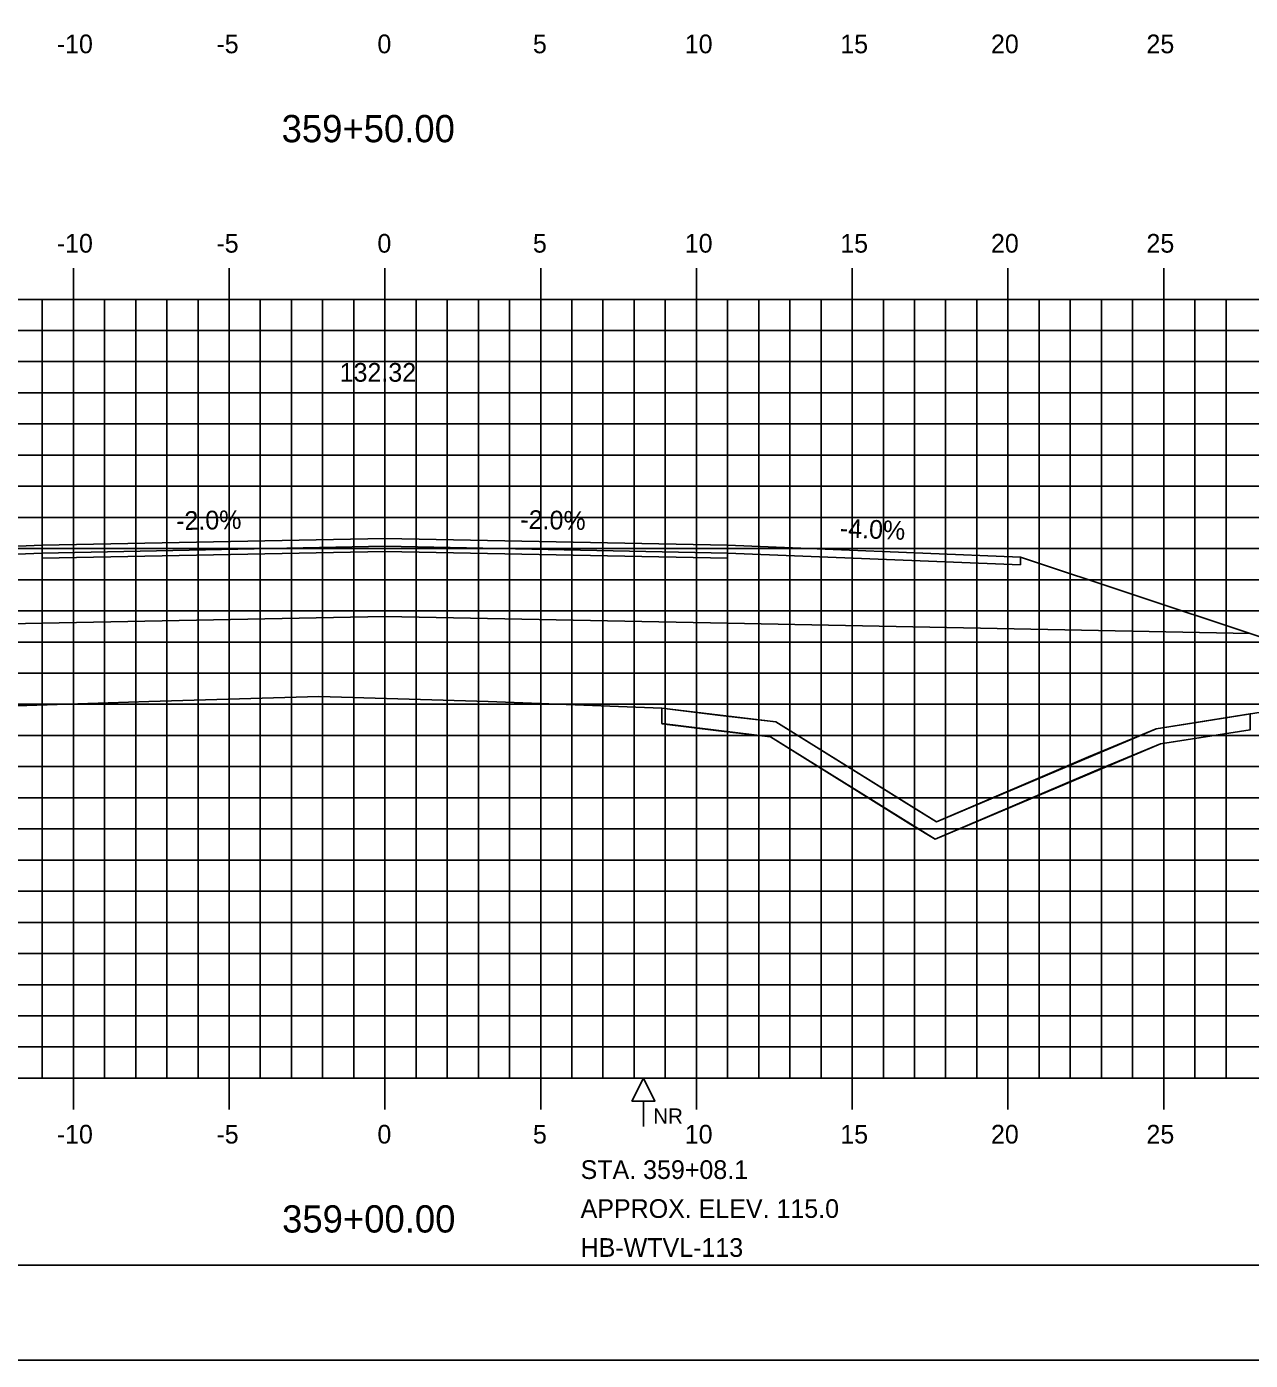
# Model space of a CAD drawing. Extents: x 1146303 to 1146473, y 608981 to 609091.
# Drawn here: x 1146374.41 to 1146413.69, y 608981.28 to 609024.09 of the extents above; entities that cross this region are included whole.
import ezdxf

# ---------------------------------------------------------------- set-up
doc = ezdxf.new("R2010")
doc.units = 0
for name, color, linetype in [('ANNOTATION', 7, 'Continuous'), ('BORDER', 7, 'Continuous'), ('D_Roadway_Centerline', 7, 'Continuous'), ('D_Roadway_Centerline_Text', 7, 'Continuous'), ('D_Roadway_Edge_Shoulder', 7, 'Continuous'), ('D_Roadway_Edge_TW', 7, 'Continuous'), ('D_Roadway_Pavement', 7, 'Continuous'), ('D_Roadway_SubGrade', 7, 'Continuous'), ('H_V ANNOTATION', 7, 'Continuous'), ('MAJOR', 7, 'Continuous'), ('MINOR', 7, 'Continuous'), ('PLOT BOUNDARY', 7, 'Continuous'), ('ROCKS', 7, 'Continuous'), ('S_Roadway_Centerline', 7, 'Continuous'), ('SHADING', 7, 'Continuous')]:
    doc.layers.add(name, color=color, linetype=linetype)

msp = doc.modelspace()

# ---------------------------------------------------------------- linework, layer by layer
msp.add_lwpolyline([(1146341.288, 608998.284), (1146357.382, 609003.649), (1146360.382, 609004.649), (1146367.914, 609007.159), (1146367.915, 609007.159), (1146374.915, 609007.439), (1146385.915, 609007.659), (1146396.915, 609007.439), (1146406.316, 609007.063), (1146413.695, 609004.604), (1146416.695, 609003.604), (1146418.924, 609002.861)])
at = {"layer": 'BORDER'}
msp.add_lwpolyline([(1146310.915, 608984.335), (1146470.915, 608984.335), (1146470.915, 609089.335), (1146310.915, 609089.335)], close=True, dxfattribs=at)
at = {"layer": 'D_Roadway_Edge_Shoulder'}
for points in [[(1146374.915, 609007.439), (1146367.915, 609007.159), (1146367.915, 609006.909), (1146374.915, 609007.189)], [(1146396.915, 609007.439), (1146406.316, 609007.063), (1146406.316, 609006.813), (1146396.915, 609007.189)]]:
    msp.add_lwpolyline(points, close=True, dxfattribs=at)
at = {"layer": 'D_Roadway_Edge_TW'}
msp.add_lwpolyline([(1146374.915, 609007.189), (1146374.915, 609007.439), (1146385.915, 609007.659), (1146396.915, 609007.439), (1146396.915, 609007.189), (1146385.915, 609007.409)], close=True, dxfattribs=at)
at = {"layer": 'D_Roadway_Pavement'}
msp.add_lwpolyline([(1146374.915, 609007.023), (1146374.915, 609007.189), (1146385.915, 609007.409), (1146396.915, 609007.189), (1146396.915, 609007.023), (1146385.915, 609007.243)], close=True, dxfattribs=at)
at = {"layer": 'D_Roadway_SubGrade'}
for p, q in [((1146394.809, 609002.215), (1146394.809, 609001.715)), ((1146413.695, 609002.025), (1146413.695, 609001.52))]:
    msp.add_line(p, q, dxfattribs=at)
for points in [[(1146374.915, 609007.023), (1146374.915, 609007.189), (1146367.915, 609006.909), (1146367.915, 609007.159), (1146367.914, 609007.159), (1146360.382, 609004.649), (1146374.915, 609004.939)], [(1146374.915, 609004.939), (1146374.915, 609007.023), (1146385.915, 609007.243), (1146396.915, 609007.023), (1146396.915, 609004.939), (1146385.915, 609005.159)], [(1146396.915, 609007.023), (1146396.915, 609007.189), (1146406.316, 609006.813), (1146406.316, 609007.063), (1146406.316, 609007.063), (1146413.695, 609004.604), (1146396.915, 609004.939)]]:
    msp.add_lwpolyline(points, close=True, dxfattribs=at)
msp.add_lwpolyline([(1146394.809, 609001.712), (1146396.623, 609001.482), (1146398.295, 609001.291), (1146402.801, 608998.475), (1146403.578, 608998.007), (1146408.695, 609000.193), (1146410.812, 609001.067), (1146412.113, 609001.267), (1146413.695, 609001.52)], dxfattribs=at)
at = {"layer": 'MAJOR'}
for p, q in [((1146375.915, 609016.337), (1146375.915, 609015.335)), ((1146380.915, 609016.337), (1146380.915, 609015.335)), ((1146385.915, 609016.337), (1146385.915, 609015.335)), ((1146390.915, 609016.337), (1146390.915, 609015.335)), ((1146395.915, 609016.337), (1146395.915, 609015.335)), ((1146400.915, 609016.337), (1146400.915, 609015.335)), ((1146405.915, 609016.337), (1146405.915, 609015.335)), ((1146410.915, 609016.337), (1146410.915, 609015.335)), ((1146315.915, 609015.335), (1146455.915, 609015.335)), ((1146315.915, 609015.335), (1146455.915, 609015.335)), ((1146375.915, 608990.335), (1146375.915, 609015.335)), ((1146380.915, 608990.335), (1146380.915, 609015.335)), ((1146385.915, 608990.335), (1146385.915, 609015.335)), ((1146390.915, 608990.335), (1146390.915, 609015.335)), ((1146395.915, 608990.335), (1146395.915, 609015.335)), ((1146400.915, 608990.335), (1146400.915, 609015.335)), ((1146405.915, 608990.335), (1146405.915, 609015.335)), ((1146410.915, 608990.335), (1146410.915, 609015.335)), ((1146315.915, 609010.335), (1146455.915, 609010.335)), ((1146315.915, 609005.335), (1146455.915, 609005.335)), ((1146315.915, 609000.335), (1146455.915, 609000.335)), ((1146315.915, 608995.335), (1146455.915, 608995.335)), ((1146315.915, 608990.335), (1146455.915, 608990.335)), ((1146315.915, 608990.335), (1146455.915, 608990.335)), ((1146375.915, 608989.333), (1146375.915, 608990.335)), ((1146380.915, 608989.333), (1146380.915, 608990.335)), ((1146385.915, 608989.333), (1146385.915, 608990.335)), ((1146390.915, 608989.333), (1146390.915, 608990.335)), ((1146395.915, 608989.333), (1146395.915, 608990.335)), ((1146400.915, 608989.333), (1146400.915, 608990.335)), ((1146405.915, 608989.333), (1146405.915, 608990.335)), ((1146410.915, 608989.333), (1146410.915, 608990.335))]:
    msp.add_line(p, q, dxfattribs=at)
at = {"layer": 'MINOR'}
for p, q in [((1146374.915, 608990.335), (1146374.915, 609015.335)), ((1146376.915, 608990.335), (1146376.915, 609015.335)), ((1146377.915, 608990.335), (1146377.915, 609015.335)), ((1146378.915, 608990.335), (1146378.915, 609015.335)), ((1146379.915, 608990.335), (1146379.915, 609015.335)), ((1146381.915, 608990.335), (1146381.915, 609015.335)), ((1146382.915, 608990.335), (1146382.915, 609015.335)), ((1146383.915, 608990.335), (1146383.915, 609015.335)), ((1146384.915, 608990.335), (1146384.915, 609015.335)), ((1146386.915, 608990.335), (1146386.915, 609015.335)), ((1146387.915, 608990.335), (1146387.915, 609015.335)), ((1146388.915, 608990.335), (1146388.915, 609015.335)), ((1146389.915, 608990.335), (1146389.915, 609015.335)), ((1146391.915, 608990.335), (1146391.915, 609015.335)), ((1146392.915, 608990.335), (1146392.915, 609015.335)), ((1146393.915, 608990.335), (1146393.915, 609015.335)), ((1146394.915, 608990.335), (1146394.915, 609015.335)), ((1146396.915, 608990.335), (1146396.915, 609015.335)), ((1146397.915, 608990.335), (1146397.915, 609015.335)), ((1146398.915, 608990.335), (1146398.915, 609015.335)), ((1146399.915, 608990.335), (1146399.915, 609015.335)), ((1146401.915, 608990.335), (1146401.915, 609015.335)), ((1146402.915, 608990.335), (1146402.915, 609015.335)), ((1146403.915, 608990.335), (1146403.915, 609015.335)), ((1146404.915, 608990.335), (1146404.915, 609015.335)), ((1146406.915, 608990.335), (1146406.915, 609015.335)), ((1146407.915, 608990.335), (1146407.915, 609015.335)), ((1146408.915, 608990.335), (1146408.915, 609015.335)), ((1146409.915, 608990.335), (1146409.915, 609015.335)), ((1146411.915, 608990.335), (1146411.915, 609015.335)), ((1146412.915, 608990.335), (1146412.915, 609015.335)), ((1146315.915, 609014.335), (1146455.915, 609014.335)), ((1146315.915, 609013.335), (1146455.915, 609013.335)), ((1146315.915, 609012.335), (1146455.915, 609012.335)), ((1146315.915, 609011.335), (1146455.915, 609011.335)), ((1146315.915, 609009.335), (1146455.915, 609009.335)), ((1146315.915, 609008.335), (1146455.915, 609008.335)), ((1146315.915, 609007.335), (1146455.915, 609007.335)), ((1146315.915, 609006.335), (1146455.915, 609006.335)), ((1146315.915, 609004.335), (1146455.915, 609004.335)), ((1146315.915, 609003.335), (1146455.915, 609003.335)), ((1146315.915, 609002.335), (1146455.915, 609002.335)), ((1146315.915, 609001.335), (1146455.915, 609001.335)), ((1146315.915, 608999.335), (1146455.915, 608999.335)), ((1146315.915, 608998.335), (1146455.915, 608998.335)), ((1146315.915, 608997.335), (1146455.915, 608997.335)), ((1146315.915, 608996.335), (1146455.915, 608996.335)), ((1146315.915, 608994.335), (1146455.915, 608994.335)), ((1146315.915, 608993.335), (1146455.915, 608993.335)), ((1146315.915, 608992.335), (1146455.915, 608992.335)), ((1146315.915, 608991.335), (1146455.915, 608991.335))]:
    msp.add_line(p, q, dxfattribs=at)
at = {"layer": 'PLOT BOUNDARY'}
msp.add_lwpolyline([(1146302.822, 608981.276), (1146472.822, 608981.276), (1146472.822, 609091.276), (1146302.822, 609091.276)], close=True, dxfattribs=at)
at = {"layer": 'ROCKS'}
for p, q in [((1146394.584, 608990.335), (1146393.846, 608990.335)), ((1146394.215, 608989.597), (1146394.215, 608988.782))]:
    msp.add_line(p, q, dxfattribs=at)
msp.add_lwpolyline([(1146394.215, 608990.335), (1146394.584, 608989.597), (1146393.846, 608989.597)], close=True, dxfattribs=at)
at = {"layer": 'S_Roadway_Centerline'}
msp.add_lwpolyline([(1146333.102, 608997.996), (1146337.13, 608998.116), (1146349.153, 608998.601), (1146351.613, 608998.852), (1146359.482, 608999.63), (1146363.256, 609000.633), (1146368.628, 609001.831), (1146370.301, 609001.988), (1146372.447, 609002.232), (1146378.334, 609002.421), (1146383.797, 609002.585), (1146389.233, 609002.425), (1146394.809, 609002.215), (1146396.683, 609001.977), (1146398.464, 609001.775), (1146403.062, 608998.9), (1146403.617, 608998.566), (1146408.502, 609000.653), (1146410.677, 609001.551), (1146412.036, 609001.76), (1146432.73, 609005.067)], dxfattribs=at)
at = {"layer": 'SHADING'}
msp.add_lwpolyline([(1146394.809, 609002.215), (1146394.809, 609001.715), (1146398.295, 609001.291), (1146403.578, 608998.007), (1146410.812, 609001.067), (1146413.695, 609001.52), (1146413.695, 609002.025), (1146410.677, 609001.551), (1146403.617, 608998.566), (1146398.464, 609001.775)], close=True, dxfattribs=at)

# ---------------------------------------------------------------- texts
at = {"layer": 'ANNOTATION'}
for s, rotation, p in [('-2.0%', 1.1458, (1146379.218, 609007.926)), ('-2.0%', 358.8542, (1146390.258, 609007.973)), ('-4.0%', 357.7094, (1146400.511, 609007.696))]:
    msp.add_text(s, height=0.6, rotation=rotation, dxfattribs=at).set_placement(p)
at = {"layer": 'D_Roadway_Centerline'}
for s, p in [('C', (1146385.909, 609007.659)), ('L', (1146385.915, 609007.652))]:
    msp.add_text(s, height=0.0146, dxfattribs=at).set_placement(p)
at = {"layer": 'D_Roadway_Centerline_Text'}
msp.add_text('132.32', height=0.6, dxfattribs=at).set_placement((1146384.462, 609012.691))
at = {"layer": 'H_V ANNOTATION'}
for s, height, p in [('-10', 0.6, (1146375.38, 609023.235)), ('-5', 0.6, (1146380.505, 609023.235)), ('0', 0.6, (1146385.674, 609023.235)), ('5', 0.6, (1146390.666, 609023.235)), ('10', 0.6, (1146395.54, 609023.235)), ('15', 0.6, (1146400.532, 609023.235)), ('20', 0.6, (1146405.369, 609023.235)), ('25', 0.6, (1146410.361, 609023.235)), ('359+50.00', 0.875, (1146382.598, 609020.378)), ('-10', 0.6, (1146375.38, 609016.835)), ('-5', 0.6, (1146380.505, 609016.835)), ('0', 0.6, (1146385.674, 609016.835)), ('5', 0.6, (1146390.666, 609016.835)), ('10', 0.6, (1146395.54, 609016.835)), ('15', 0.6, (1146400.532, 609016.835)), ('20', 0.6, (1146405.369, 609016.835)), ('25', 0.6, (1146410.361, 609016.835)), ('-10', 0.6, (1146375.38, 608988.235)), ('-5', 0.6, (1146380.505, 608988.235)), ('0', 0.6, (1146385.674, 608988.235)), ('5', 0.6, (1146390.666, 608988.235)), ('10', 0.6, (1146395.54, 608988.235)), ('15', 0.6, (1146400.532, 608988.235)), ('20', 0.6, (1146405.369, 608988.235)), ('25', 0.6, (1146410.361, 608988.235)), ('359+00.00', 0.875, (1146382.614, 608985.378))]:
    msp.add_text(s, height=height, dxfattribs=at).set_placement(p)
at = {"layer": 'ROCKS'}
msp.add_text('NR', height=0.4921, dxfattribs=at).set_placement((1146394.53, 608988.87))
for s, p in [('STA. 359+08.1', (1146392.197, 608987.098)), ('APPROX. ELEV. 115.0', (1146392.197, 608985.848)), ('HB-WTVL-113', (1146392.197, 608984.598))]:
    msp.add_text(s, height=0.6, rotation=360, dxfattribs=at).set_placement(p)
at = {"layer": 'S_Roadway_Centerline'}
for s, p in [('L', (1146383.789, 609002.578)), ('C', (1146383.792, 609002.585))]:
    msp.add_text(s, height=0.0146, dxfattribs=at).set_placement(p)

doc.saveas('drawing.dxf')
